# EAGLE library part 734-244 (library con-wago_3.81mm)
Serie 734, Stiftleiste (für Leiterplatten) Einlötstift gerade 1 x 1 mm / Series 734, Male header (for PCBs) Straight solder pin 1 x 1 mm Polzahl / Pole No.: 14 Rastermaß / Pitch: 3.81 mm Bemessungsspannung / Rated Voltage: 160 V Nennstrom / Nominal Current: 10 A Lötstiftlänge: / Solder Pin Length: 4.5 mm Farbe / Color: orange / orange Stand: 01.01.2012. Die jeweils aktuellen Daten zu diesem Artikel finden Sie in unserem Produktkatalog, den Sie unter www.wago.com einsehen können. As of: 01/01/2012. Please find the newest data for this article in our product catalogue, which can be viewed under www.wago.com.
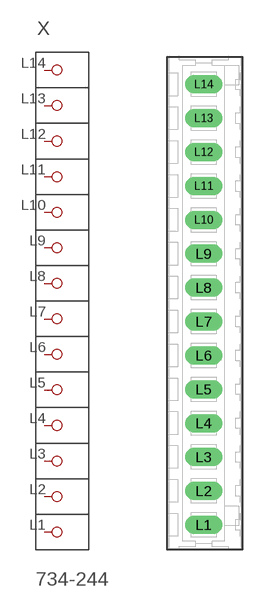
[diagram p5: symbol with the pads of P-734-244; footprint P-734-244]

Designator prefix X

## 734-244  [P-734-244]
L1  P1
L2  P2
L3  P3
L4  P4
L5  P5
L6  P6
L7  P7
L8  P8
L9  P9
L10  P10
L11  P11
L12  P12
L13  P13
L14  P14

## Footprint P-734-244 (pad centres in mm)
drill 1.4 long: L1 -0.1,-24.915; L2 -0.1,-21.105; L3 -0.1,-17.295; L4 -0.1,-13.485; L5 -0.1,-9.675; L6 -0.1,-5.865; L7 -0.1,-2.055; L8 -0.1,1.755; L9 -0.1,5.565; L10 -0.1,9.375; L11 -0.1,13.185; L12 -0.1,16.995; L13 -0.1,20.805; L14 -0.1,24.615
